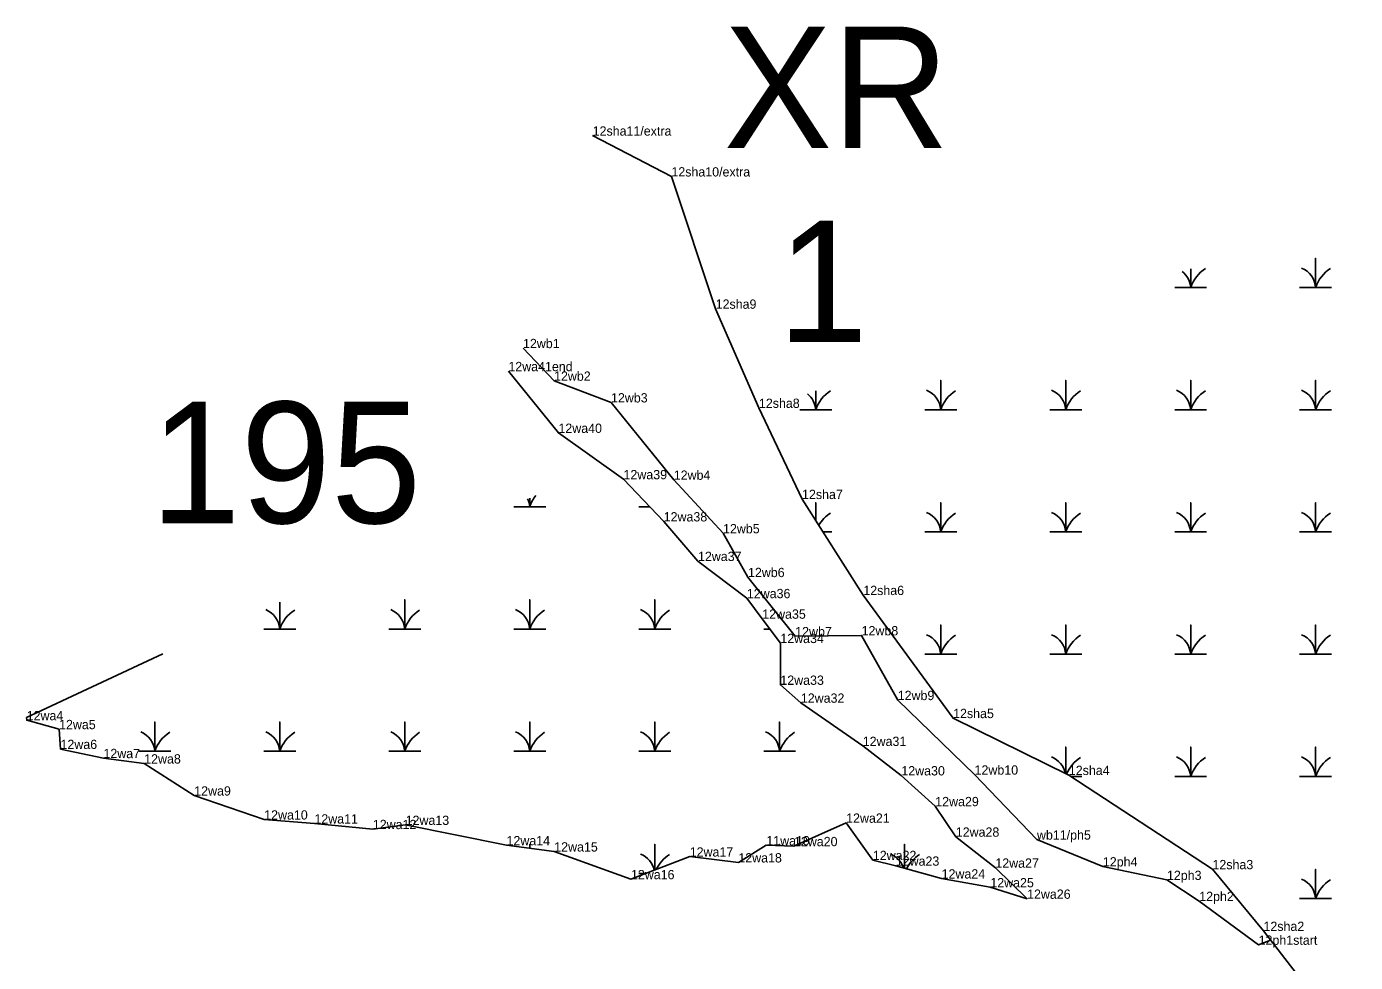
# Model space of a CAD drawing. Extents: x 2072529 to 2268796, y 436423 to 470397.
# Drawn here: x 2228629 to 2229344, y 451351 to 451855 of the extents above; entities that cross this region are included whole.
import ezdxf

# ---------------------------------------------------------------- set-up
doc = ezdxf.new("R2010")
doc.units = 0
for name, color, linetype in [('Default', 7, 'Continuous'), ('Exist Environmental Wetland Boundary', 7, 'Continuous'), ('Exist Environmental Wetland Boundary Cogo Comment', 7, 'Continuous'), ('Exist Environmental Wetland Boundary Cogo Point CELL', 7, 'Continuous'), ('Exist Hydro Jurisdictional Stream or Body of Water NEU Mitigable', 7, 'Continuous'), ('Exist Hydro Jurisdictional Stream or Body of Water NEU Mitigable Cogo Comment', 7, 'Continuous'), ('Exist Hydro Swamp or Marsh', 7, 'Continuous')]:
    doc.layers.add(name, color=color, linetype=linetype)

msp = doc.modelspace()

# ---------------------------------------------------------------- linework, layer by layer
at = {"layer": 'Exist Environmental Wetland Boundary'}
for points in [[(2228896.35, 451681.44), (2228913.06, 451663.89), (2228943.71, 451652.21), (2228977.48, 451610.58), (2229003.99, 451581.76), (2229017.42, 451558.18), (2229042.83, 451526.35), (2229078.56, 451526.82), (2229097.99, 451491.97), (2229139.35, 451451.85), (2229172.92, 451416.85), (2229208.39, 451402.4), (2229242.87, 451395.13), (2229260.24, 451383.8), (2229292.19, 451360.24), (2229298.62, 451362.75)], [(2228702.56, 451516.82), (2228629.21, 451482.6), (2228629.27, 451481.11), (2228646.71, 451476.32), (2228647.48, 451465.64), (2228670.58, 451460.73), (2228692.51, 451457.82), (2228719.44, 451440.57), (2228757.1, 451427.66), (2228784.1, 451425.51), (2228815.54, 451422.51), (2228833.2, 451424.77), (2228887.49, 451413.82), (2228913.17, 451410.45), (2228954.45, 451395.53), (2228986.06, 451407.71), (2229012.23, 451404.56), (2229027.28, 451413.79), (2229042.17, 451413.32), (2229070.24, 451425.93), (2229084.61, 451405.84), (2229096.95, 451402.8), (2229121.62, 451395.91), (2229147.82, 451391.18), (2229167.6, 451385), (2229150.52, 451401.73), (2229129.24, 451418.42), (2229118.19, 451434.85), (2229099.93, 451451.42), (2229079.18, 451467.27), (2229045.87, 451490.55), (2229034.83, 451500.19), (2229034.82, 451522.68), (2229025.1, 451535.77), (2229016.83, 451546.84), (2228990.51, 451566.84), (2228972.06, 451588.15), (2228950.44, 451610.86), (2228915.42, 451635.83), (2228888.48, 451669.05)]]:
    msp.add_lwpolyline(points, dxfattribs=at)
at = {"layer": 'Exist Environmental Wetland Boundary Cogo Point CELL'}
for p, q in [((2228933.83, 451795.85), (2228933.83, 451795.85)), ((2228976.21, 451773.86), (2228976.21, 451773.86)), ((2229000.02, 451702.66), (2229000.02, 451702.66)), ((2228896.35, 451681.44), (2228896.35, 451681.44)), ((2228888.48, 451669.05), (2228888.48, 451669.05)), ((2228913.06, 451663.89), (2228913.06, 451663.89)), ((2228943.71, 451652.21), (2228943.71, 451652.21)), ((2229023.31, 451649.28), (2229023.31, 451649.28)), ((2228915.42, 451635.83), (2228915.42, 451635.83)), ((2228950.44, 451610.86), (2228950.44, 451610.86)), ((2228977.48, 451610.58), (2228977.48, 451610.58)), ((2229046.5, 451600.21), (2229046.5, 451600.21)), ((2228972.06, 451588.15), (2228972.06, 451588.15)), ((2229003.99, 451581.76), (2229003.99, 451581.76)), ((2228990.51, 451566.84), (2228990.51, 451566.84)), ((2229017.42, 451558.18), (2229017.42, 451558.18)), ((2229016.83, 451546.84), (2229016.83, 451546.84)), ((2229079.47, 451548.53), (2229079.47, 451548.53)), ((2229025.02, 451535.77), (2229025.02, 451535.77)), ((2229034.82, 451522.68), (2229034.82, 451522.68)), ((2229042.83, 451526.35), (2229042.83, 451526.35)), ((2229078.56, 451526.82), (2229078.56, 451526.82)), ((2229034.83, 451500.19), (2229034.83, 451500.19)), ((2229097.99, 451491.97), (2229097.99, 451491.97)), ((2229045.87, 451490.55), (2229045.87, 451490.55)), ((2228629.27, 451481.11), (2228629.27, 451481.11)), ((2229127.8, 451482.28), (2229127.8, 451482.28)), ((2228646.71, 451476.32), (2228646.71, 451476.32)), ((2228647.48, 451465.64), (2228647.48, 451465.64)), ((2229079.18, 451467.27), (2229079.18, 451467.27)), ((2228670.58, 451460.73), (2228670.58, 451460.73)), ((2228692.51, 451457.82), (2228692.51, 451457.82)), ((2229099.93, 451451.42), (2229099.93, 451451.42)), ((2229139.35, 451451.85), (2229139.35, 451451.85)), ((2229190.08, 451451.65), (2229190.08, 451451.65)), ((2228719.44, 451440.57), (2228719.44, 451440.57)), ((2229118.19, 451434.85), (2229118.19, 451434.85)), ((2228757.1, 451427.66), (2228757.1, 451427.66)), ((2228784.1, 451425.51), (2228784.1, 451425.51)), ((2228815.54, 451422.51), (2228815.54, 451422.51)), ((2228833.2, 451424.77), (2228833.2, 451424.77)), ((2229070.24, 451425.93), (2229070.24, 451425.93)), ((2228887.49, 451413.82), (2228887.49, 451413.82)), ((2229027.28, 451413.79), (2229027.28, 451413.79)), ((2229042.17, 451413.32), (2229042.17, 451413.32)), ((2229129.24, 451418.42), (2229129.24, 451418.42)), ((2229172.92, 451416.85), (2229172.92, 451416.85)), ((2228913.17, 451410.45), (2228913.17, 451410.45)), ((2228986.06, 451407.71), (2228986.06, 451407.71)), ((2229012.23, 451404.56), (2229012.23, 451404.56)), ((2229084.61, 451405.84), (2229084.61, 451405.84)), ((2229096.95, 451402.8), (2229096.95, 451402.8)), ((2229150.52, 451401.73), (2229150.52, 451401.73)), ((2229208.39, 451402.4), (2229208.39, 451402.4)), ((2229267.38, 451400.92), (2229267.38, 451400.92)), ((2228954.45, 451395.53), (2228954.45, 451395.53)), ((2229121.62, 451395.91), (2229121.62, 451395.91)), ((2229242.87, 451395.13), (2229242.87, 451395.13)), ((2229147.82, 451391.18), (2229147.82, 451391.18)), ((2229167.6, 451385), (2229167.6, 451385)), ((2229260.24, 451383.8), (2229260.24, 451383.8)), ((2229294.81, 451367.69), (2229294.81, 451367.69)), ((2229292.19, 451360.24), (2229292.19, 451360.24))]:
    msp.add_line(p, q, dxfattribs=at)
at = {"layer": 'Exist Hydro Jurisdictional Stream or Body of Water NEU Mitigable'}
msp.add_lwpolyline([(2228933.83, 451795.85), (2228976.21, 451773.86), (2229000.02, 451702.66), (2229023.31, 451649.28), (2229046.5, 451600.21), (2229079.47, 451548.53), (2229127.8, 451482.28), (2229190.08, 451451.65), (2229267.38, 451400.92), (2229294.81, 451367.69), (2229366.97, 451274.18), (2229367.34, 451273.73), (2229395.61, 451201.43), (2229409.63, 451167.28), (2229427.34, 451140.76), (2229444.31, 451111.6), (2229465.09, 451122.24), (2229488.39, 451115.29), (2229545.28, 451079.31), (2229562.75, 451050.09)], dxfattribs=at)
at = {"layer": 'Exist Hydro Swamp or Marsh'}
for points in [[(2229314.28, 451714.08), (2229322.88, 451714.08), (2229322.88, 451729.86), (2229322.88, 451714.08), (2229331.48, 451714.08)], [(2229247.03, 451714.08), (2229255.63, 451714.08), (2229255.63, 451724.17)], [(2229255.63, 451724.17), (2229255.63, 451714.08), (2229264.23, 451714.08)], [(2229112.53, 451648.28), (2229121.13, 451648.28), (2229121.13, 451664.06), (2229121.13, 451648.28), (2229129.73, 451648.28)], [(2229179.78, 451648.28), (2229188.38, 451648.28), (2229188.38, 451664.06), (2229188.38, 451648.28), (2229196.98, 451648.28)], [(2229247.03, 451648.28), (2229255.63, 451648.28), (2229255.63, 451664.06), (2229255.63, 451648.28), (2229264.23, 451648.28)], [(2229314.28, 451648.28), (2229322.88, 451648.28), (2229322.88, 451664.06), (2229322.88, 451648.28), (2229331.48, 451648.28)], [(2229045.28, 451648.28), (2229053.88, 451648.28), (2229053.88, 451658.41)], [(2229053.88, 451658.41), (2229053.88, 451648.28), (2229062.48, 451648.28)], [(2228891.36, 451596.01), (2228899.96, 451596.01), (2228899.96, 451600.75)], [(2228899.96, 451600.75), (2228899.96, 451596.01), (2228908.56, 451596.01)], [(2228958.61, 451596.01), (2228964.58, 451596.01)], [(2229053.88, 451588.64), (2229053.88, 451598.26), (2229053.88, 451588.64)], [(2229112.53, 451582.48), (2229121.13, 451582.48), (2229121.13, 451598.26), (2229121.13, 451582.48), (2229129.73, 451582.48)], [(2229179.78, 451582.48), (2229188.38, 451582.48), (2229188.38, 451598.26), (2229188.38, 451582.48), (2229196.98, 451582.48)], [(2229247.03, 451582.48), (2229255.63, 451582.48), (2229255.63, 451598.26), (2229255.63, 451582.48), (2229264.23, 451582.48)], [(2229314.28, 451582.48), (2229322.88, 451582.48), (2229322.88, 451598.26), (2229322.88, 451582.48), (2229331.48, 451582.48)], [(2229057.81, 451582.48), (2229062.48, 451582.48)], [(2228756.86, 451530.21), (2228765.46, 451530.21), (2228765.46, 451544.77)], [(2228765.46, 451544.77), (2228765.46, 451530.21), (2228774.06, 451530.21)], [(2228824.11, 451530.21), (2228832.71, 451530.21), (2228832.71, 451545.99), (2228832.71, 451530.21), (2228841.31, 451530.21)], [(2228891.36, 451530.21), (2228899.96, 451530.21), (2228899.96, 451545.99), (2228899.96, 451530.21), (2228908.56, 451530.21)], [(2228958.61, 451530.21), (2228967.21, 451530.21), (2228967.21, 451545.99), (2228967.21, 451530.21), (2228975.81, 451530.21)], [(2229025.86, 451530.21), (2229029.23, 451530.21)], [(2229112.53, 451516.68), (2229121.13, 451516.68), (2229121.13, 451532.46), (2229121.13, 451516.68), (2229129.73, 451516.68)], [(2229179.78, 451516.68), (2229188.38, 451516.68), (2229188.38, 451532.46), (2229188.38, 451516.68), (2229196.98, 451516.68)], [(2229247.03, 451516.68), (2229255.63, 451516.68), (2229255.63, 451532.46), (2229255.63, 451516.68), (2229264.23, 451516.68)], [(2229314.28, 451516.68), (2229322.88, 451516.68), (2229322.88, 451532.46), (2229322.88, 451516.68), (2229331.48, 451516.68)], [(2228689.61, 451464.41), (2228698.21, 451464.41), (2228698.21, 451480.19), (2228698.21, 451464.41), (2228706.81, 451464.41)], [(2228756.86, 451464.41), (2228765.46, 451464.41), (2228765.46, 451480.19), (2228765.46, 451464.41), (2228774.06, 451464.41)], [(2228824.11, 451464.41), (2228832.71, 451464.41), (2228832.71, 451480.19), (2228832.71, 451464.41), (2228841.31, 451464.41)], [(2228891.36, 451464.41), (2228899.96, 451464.41), (2228899.96, 451480.19), (2228899.96, 451464.41), (2228908.56, 451464.41)], [(2228958.61, 451464.41), (2228967.21, 451464.41), (2228967.21, 451480.19), (2228967.21, 451464.41), (2228975.81, 451464.41)], [(2229025.86, 451464.41), (2229034.46, 451464.41), (2229034.46, 451480.19), (2229034.46, 451464.41), (2229043.06, 451464.41)], [(2229188.38, 451452.49), (2229188.38, 451466.66), (2229188.38, 451452.49)], [(2229247.03, 451450.88), (2229255.63, 451450.88), (2229255.63, 451466.66), (2229255.63, 451450.88), (2229264.23, 451450.88)], [(2229314.28, 451450.88), (2229322.88, 451450.88), (2229322.88, 451466.66), (2229322.88, 451450.88), (2229331.48, 451450.88)], [(2229191.27, 451450.88), (2229196.98, 451450.88)], [(2228899.96, 451412.19), (2228899.96, 451414.39), (2228899.96, 451412.19)], [(2228967.21, 451400.45), (2228967.21, 451414.39), (2228967.21, 451400.45)], [(2229034.46, 451413.56), (2229034.46, 451414.39), (2229034.46, 451413.56)], [(2229101.71, 451401.47), (2229101.71, 451414.39), (2229101.71, 451401.47)], [(2229314.28, 451385.08), (2229322.88, 451385.08), (2229322.88, 451400.86), (2229322.88, 451385.08), (2229331.48, 451385.08)], [(2228958.61, 451398.61), (2228962.43, 451398.61)]]:
    msp.add_lwpolyline(points, dxfattribs=at)
for centre, radius, start, end in [((2229243.36, 451713.19), 12.3, 4.14034, 51.21151), ((2229273.87, 451708.02), 19.22, 122.12745, 161.62219), ((2229310.61, 451713.19), 12.3, 4.14034, 67.53497), ((2229341.12, 451708.02), 19.22, 122.12745, 161.62219), ((2229041.61, 451647.39), 12.3, 4.14034, 50.3632), ((2229072.12, 451642.22), 19.22, 122.12745, 161.62219), ((2229108.86, 451647.39), 12.3, 4.14034, 67.53497), ((2229139.37, 451642.22), 19.22, 122.12745, 161.62219), ((2229176.11, 451647.39), 12.3, 4.14034, 67.53497), ((2229206.62, 451642.22), 19.22, 122.12745, 161.62219), ((2229243.36, 451647.39), 12.3, 4.14034, 67.53497), ((2229273.87, 451642.22), 19.22, 122.12745, 161.62219), ((2229310.61, 451647.39), 12.3, 4.14034, 67.53497), ((2229341.12, 451642.22), 19.22, 122.12745, 161.62219), ((2228887.69, 451595.12), 12.3, 4.14034, 24.96517), ((2228918.2, 451589.95), 19.22, 140.99582, 161.62219), ((2229072.12, 451576.42), 19.22, 122.12745, 149.79744), ((2229108.86, 451581.59), 12.3, 4.14034, 67.53497), ((2229139.37, 451576.42), 19.22, 122.12745, 161.62219), ((2229176.11, 451581.59), 12.3, 4.14034, 67.53497), ((2229206.62, 451576.42), 19.22, 122.12745, 161.62219), ((2229243.36, 451581.59), 12.3, 4.14034, 67.53497), ((2229273.87, 451576.42), 19.22, 122.12745, 161.62219), ((2229310.61, 451581.59), 12.3, 4.14034, 67.53497), ((2229341.12, 451576.42), 19.22, 122.12745, 161.62219), ((2228753.19, 451529.32), 12.3, 4.14034, 67.53497), ((2228783.7, 451524.15), 19.22, 122.12745, 161.62219), ((2228820.44, 451529.32), 12.3, 4.14034, 67.53497), ((2228850.95, 451524.15), 19.22, 122.12745, 161.62219), ((2228887.69, 451529.32), 12.3, 4.14034, 67.53497), ((2228918.2, 451524.15), 19.22, 122.12745, 161.62219), ((2228954.94, 451529.32), 12.3, 4.14034, 67.53497), ((2228985.45, 451524.15), 19.22, 122.12745, 161.62219), ((2229108.86, 451515.79), 12.3, 4.14034, 67.53497), ((2229139.37, 451510.62), 19.22, 122.12745, 161.62219), ((2229176.11, 451515.79), 12.3, 4.14034, 67.53497), ((2229206.62, 451510.62), 19.22, 122.12745, 161.62219), ((2229243.36, 451515.79), 12.3, 4.14034, 67.53497), ((2229273.87, 451510.62), 19.22, 122.12745, 161.62219), ((2229310.61, 451515.79), 12.3, 4.14034, 67.53497), ((2229341.12, 451510.62), 19.22, 122.12745, 161.62219), ((2228685.94, 451463.52), 12.3, 4.14034, 67.53497), ((2228716.45, 451458.35), 19.22, 122.12745, 161.62219), ((2228753.19, 451463.52), 12.3, 4.14034, 67.53497), ((2228783.7, 451458.35), 19.22, 122.12745, 161.62219), ((2228820.44, 451463.52), 12.3, 4.14034, 67.53497), ((2228850.95, 451458.35), 19.22, 122.12745, 161.62219), ((2228887.69, 451463.52), 12.3, 4.14034, 67.53497), ((2228918.2, 451458.35), 19.22, 122.12745, 161.62219), ((2228954.94, 451463.52), 12.3, 4.14034, 67.53497), ((2228985.45, 451458.35), 19.22, 122.12745, 161.62219), ((2229022.19, 451463.52), 12.3, 4.14034, 67.53497), ((2229052.7, 451458.35), 19.22, 122.12745, 161.62219), ((2229176.11, 451449.99), 12.3, 12.32484, 67.53497), ((2229206.62, 451444.82), 19.22, 122.12745, 157.28395), ((2229243.36, 451449.99), 12.3, 4.14034, 67.53497), ((2229273.87, 451444.82), 19.22, 122.12745, 161.62219), ((2229310.61, 451449.99), 12.3, 4.14034, 67.53497), ((2229341.12, 451444.82), 19.22, 122.12745, 161.62219), ((2228954.94, 451397.72), 12.3, 12.36667, 67.53497), ((2228985.45, 451392.55), 19.22, 122.12745, 154.61143), ((2229089.44, 451397.72), 12.3, 18.60426, 67.53497), ((2229119.95, 451392.55), 19.22, 122.12745, 153.32917), ((2229310.61, 451384.19), 12.3, 4.14034, 67.53497), ((2229341.12, 451379.02), 19.22, 122.12745, 161.62219)]:
    msp.add_arc(centre, radius, start, end, dxfattribs=at)

# ---------------------------------------------------------------- texts
at = {"layer": 'Default'}
for s, p in [('XR', (2229004.33, 451789.23)), ('1', (2229033.38, 451684.69)), ('195', (2228695.81, 451587.22))]:
    msp.add_text(s, height=65.34, dxfattribs=at).set_placement(p)
at = {"layer": 'Exist Environmental Wetland Boundary Cogo Comment'}
for s, p in [('12wb1', (2228896.35, 451681.44)), ('12wa41end', (2228888.48, 451669.05)), ('12wb2', (2228913.06, 451663.89)), ('12wb3', (2228943.71, 451652.21)), ('12wa40', (2228915.42, 451635.83)), ('12wa39', (2228950.44, 451610.86)), ('12wb4', (2228977.48, 451610.58)), ('12wa38', (2228972.06, 451588.15)), ('12wb5', (2229003.99, 451581.76)), ('12wa37', (2228990.51, 451566.84)), ('12wb6', (2229017.42, 451558.18)), ('12wa36', (2229016.83, 451546.84)), ('12wa35', (2229025.1, 451535.77)), ('12wa34', (2229034.82, 451522.68)), ('12wb7', (2229042.83, 451526.35)), ('12wa33', (2229034.83, 451500.19)), ('12wa32', (2229045.87, 451490.55)), ('12wa4', (2228629.27, 451481.11)), ('12wa5', (2228646.71, 451476.32)), ('12wa6', (2228647.48, 451465.64)), ('12wa31', (2229079.18, 451467.27)), ('12wa7', (2228670.58, 451460.73)), ('12wa8', (2228692.51, 451457.82)), ('12wa30', (2229099.93, 451451.42)), ('12wb10', (2229139.35, 451451.85)), ('12wa9', (2228719.44, 451440.57)), ('12wa29', (2229118.19, 451434.85)), ('12wa10', (2228757.1, 451427.66)), ('12wa11', (2228784.1, 451425.51)), ('12wa12', (2228815.54, 451422.51)), ('12wa13', (2228833.2, 451424.77)), ('12wa21', (2229070.24, 451425.93)), ('12wa28', (2229129.24, 451418.42)), ('wb11/ph5', (2229172.92, 451416.85)), ('12wa14', (2228887.49, 451413.82)), ('12wa15', (2228913.17, 451410.45)), ('11wa19', (2229027.28, 451413.79)), ('12wa20', (2229042.17, 451413.32)), ('12wa17', (2228986.06, 451407.71)), ('12wa18', (2229012.23, 451404.56)), ('12wa22', (2229084.61, 451405.84)), ('12wa23', (2229096.95, 451402.8)), ('12wa27', (2229150.52, 451401.73)), ('12ph4', (2229208.39, 451402.4)), ('12wa16', (2228954.45, 451395.53)), ('12wa24', (2229121.62, 451395.91)), ('12ph3', (2229242.87, 451395.13)), ('12wa25', (2229147.82, 451391.18)), ('12wa26', (2229167.6, 451385)), ('12ph2', (2229260.24, 451383.8)), ('12ph1start', (2229292.19, 451360.24))]:
    msp.add_text(s, height=5, dxfattribs=at).set_placement(p)
at = {"layer": 'Exist Hydro Jurisdictional Stream or Body of Water NEU Mitigable Cogo Comment'}
for s, p in [('12sha11/extra', (2228933.83, 451795.85)), ('12sha10/extra', (2228976.21, 451773.86)), ('12sha9', (2229000.02, 451702.66)), ('12sha8', (2229023.31, 451649.28)), ('12sha7', (2229046.5, 451600.21)), ('12sha6', (2229079.47, 451548.53)), ('12wb8', (2229078.56, 451526.82)), ('12wb9', (2229097.99, 451491.97)), ('12sha5', (2229127.8, 451482.28)), ('12sha4', (2229190.08, 451451.65)), ('12sha3', (2229267.38, 451400.92)), ('12sha2', (2229294.81, 451367.69))]:
    msp.add_text(s, height=5, dxfattribs=at).set_placement(p)

doc.saveas('drawing.dxf')
